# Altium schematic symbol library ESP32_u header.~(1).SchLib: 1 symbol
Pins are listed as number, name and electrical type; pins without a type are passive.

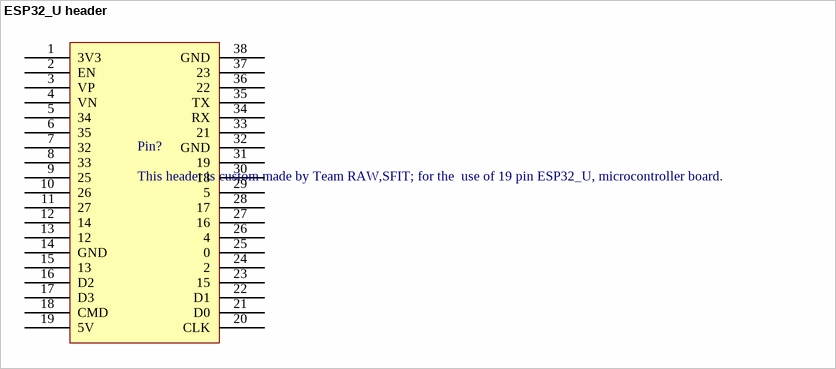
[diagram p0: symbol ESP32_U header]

## ESP32_U header
designator Pin?, comment This header is custom made by Team RAW,SFIT; for the  use of 19 pin ESP32_U, microcontroller board.
Custom banana pada; pin numbers: 19; pitch: 100mils
footprint ESP32_uFootprint (This is a custom footprint made by Team RAW. The library is dedicated for ESP32_u)
pins: 1 3V3, 2 EN, 3 VP, 4 VN, 5 34, 6 35, 7 32, 8 33, 9 25, 10 26, 11 27, 12 14, 13 12, 14 GND, 15 13, 16 D2, 17 D3, 18 CMD, 19 5V, 20 CLK, 21 D0, 22 D1, 23 15, 24 2, 25 0, 26 4, 27 16, 28 17, 29 5, 30 18, 31 19, 32 GND, 33 21, 34 RX, 35 TX, 36 22, 37 23, 38 GND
